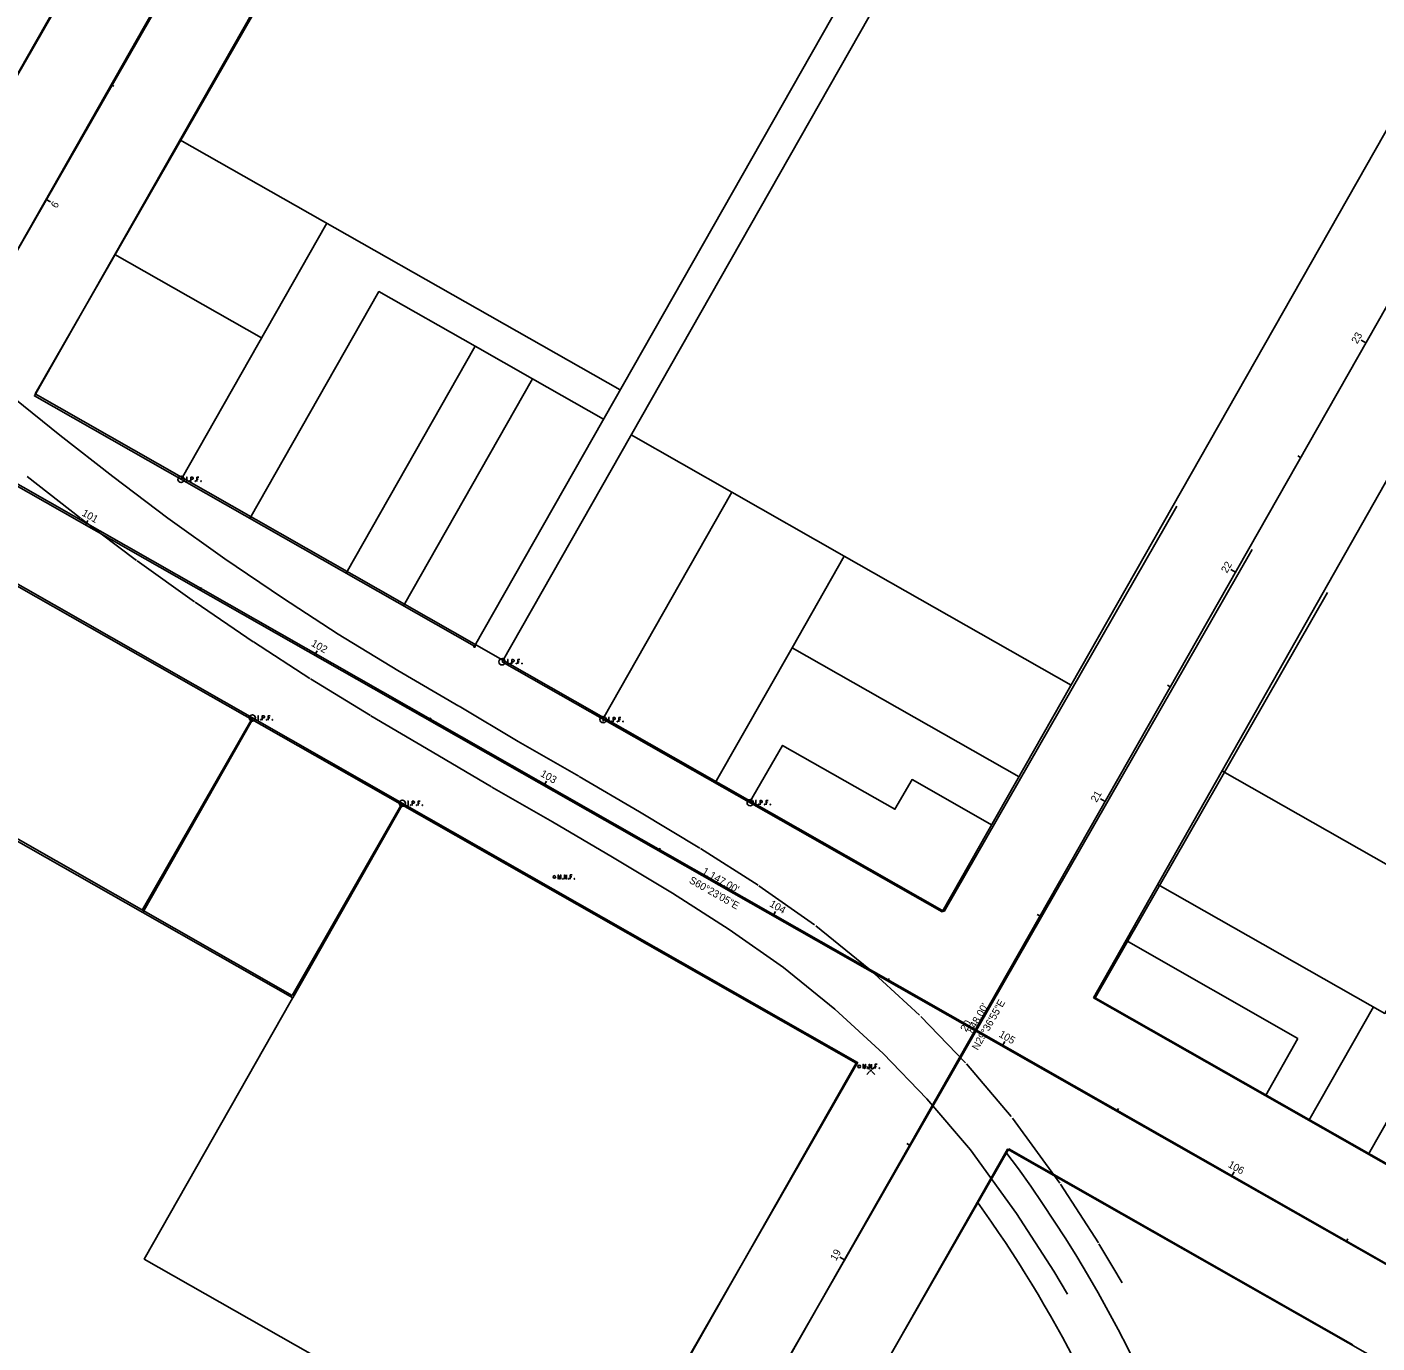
# Model space of a CAD drawing. Extents: x 119320 to 120701, y 385020 to 386199.
# Drawn here: x 119728 to 120240, y 385433 to 385932 of the extents above; entities that cross this region are included whole.
import ezdxf

# ---------------------------------------------------------------- set-up
doc = ezdxf.new("R2010")
doc.units = 0
for name, color, linetype in [('DV_X_Property_Line', 7, 'Continuous'), ('RW_X_CL', 7, 'Continuous'), ('RW_X_CL_100_Bearings', 7, 'Continuous'), ('RW_X_CL_100_Distances', 7, 'Continuous'), ('RW_X_CL_100_Stations', 7, 'Continuous'), ('RW_X_Esmt_RR', 7, 'Continuous'), ('RW_X_Fee_RW', 7, 'Continuous'), ('SC_Scratch1', 7, 'Continuous'), ('SV_X_Control_Cells_Found', 7, 'Continuous'), ('SV_X_Mon_Cells_Found', 7, 'Continuous'), ('SV_X_Shot_Marker', 7, 'Continuous')]:
    doc.layers.add(name, color=color, linetype=linetype)

msp = doc.modelspace()

# ---------------------------------------------------------------- linework, layer by layer
at = {"layer": 'DV_X_Property_Line'}
for p, q in [((119785.77, 385889.55), (119952.69, 385794.67)), ((119786.19, 385760.77), (119841.41, 385857.92)), ((119761.07, 385846.08), (119816.71, 385814.45)), ((119995.08, 385755.91), (119956.82, 385777.65)), ((119946.15, 385669.84), (119995.08, 385755.91)), ((119995.08, 385755.91), (120037.67, 385731.69)), ((119771.7, 385596.46), (119656.42, 385661.99)), ((120144.55, 385585.82), (120209.75, 385548.76)), ((120213.92, 385517.64), (120238.38, 385560.67)), ((120197.4, 385527.03), (120209.75, 385548.76))]:
    msp.add_line(p, q, dxfattribs=at)
for points in [[(119812.27, 385745.94), (119861.19, 385832.01), (119897.71, 385811.26)], [(119848.78, 385725.19), (119897.71, 385811.26), (119919.44, 385798.9)], [(119870.52, 385712.83), (119919.44, 385798.9), (119946.39, 385783.58)], [(120017.91, 385696.92), (120037.67, 385731.69), (120123.74, 385682.77)], [(119988.75, 385645.63), (120017.91, 385696.92), (120103.97, 385648)], [(119870.07, 385637.17), (119828.56, 385564.15), (119771.7, 385596.46), (119813.21, 385669.49)], [(120001.79, 385638.21), (120014.3, 385659.86), (120056.9, 385635.64), (120063.41, 385646.9), (120093.84, 385629.6)], [(120156.66, 385607.12), (120242.73, 385558.2), (120267.19, 385601.23), (120181.12, 385650.16)], [(119944.36, 385367.19), (119772.22, 385465.04), (119870.07, 385637.17)], [(120236.52, 385504.79), (120285.44, 385590.85), (120267.19, 385601.23)]]:
    msp.add_lwpolyline(points, dxfattribs=at)
for radius, start, end in [(494.53, 7.3661, 36.9032), (474.53, 17.8628, 35.8499)]:
    msp.add_arc((119703.54, 385208.72), radius, start, end, dxfattribs=at)
at = {"layer": 'RW_X_CL'}
for p, q in [((119897.55, 386152.97), (119478.5, 385415.75)), ((119880.14, 385187.44), (120299.2, 385924.66)), ((119491.69, 385890.22), (120488.85, 385323.4))]:
    msp.add_line(p, q, dxfattribs=at)
at = {"layer": 'RW_X_CL_100_Stations'}
for p, q in [((119759.68, 385910.42), (119760.72, 385909.83)), ((119734.97, 385866.95), (119736.71, 385865.96)), ((120235.45, 385812.52), (120233.71, 385813.5)), ((120210.74, 385769.05), (120209.7, 385769.64)), ((119749.89, 385743.45), (119750.88, 385745.19)), ((120186.03, 385725.58), (120184.3, 385726.57)), ((119793.36, 385718.74), (119793.95, 385719.78)), ((119836.82, 385694.03), (119837.81, 385695.77)), ((120161.33, 385682.11), (120160.28, 385682.7)), ((119880.29, 385669.32), (119880.88, 385670.36)), ((119923.76, 385644.61), (119924.75, 385646.35)), ((120136.62, 385638.64), (120134.88, 385639.63)), ((119967.23, 385619.9), (119967.82, 385620.95)), ((120010.7, 385595.19), (120011.68, 385596.93)), ((120111.91, 385595.18), (120110.87, 385595.77)), ((120054.16, 385570.49), (120054.76, 385571.53)), ((120087.2, 385551.71), (120085.46, 385552.7)), ((120097.63, 385545.78), (120098.62, 385547.52)), ((120141.1, 385521.07), (120141.69, 385522.11)), ((120062.49, 385508.24), (120061.45, 385508.83)), ((120184.57, 385496.36), (120185.56, 385498.1)), ((120228.04, 385471.65), (120228.63, 385472.69)), ((120037.78, 385464.77), (120036.04, 385465.76))]:
    msp.add_line(p, q, dxfattribs=at)
at = {"layer": 'RW_X_Esmt_RR'}
for p, q in [((119723.13, 385791.28), (119740.18, 385777.58)), ((119740.18, 385777.58), (119760.32, 385761.85)), ((119727.81, 385761.86), (119748.07, 385746.03)), ((119760.32, 385761.85), (119781.21, 385746.08)), ((119748.2, 385745.93), (119769.27, 385730.03)), ((119781.21, 385746.08), (119802.83, 385730.69)), ((119769.5, 385729.87), (119791.32, 385714.34)), ((119802.83, 385730.69), (119824.68, 385715.8)), ((119791.49, 385714.22), (119813.51, 385699.21)), ((119824.68, 385715.8), (119845.81, 385702.06)), ((119845.81, 385702.06), (119868.36, 385688.28)), ((119813.69, 385699.09), (119835.02, 385685.21)), ((119868.36, 385688.28), (119891.57, 385674.73)), ((119835.26, 385685.06), (119858.02, 385671.16)), ((119937.14, 385648.12), (119959.99, 385634.68)), ((119960.08, 385634.63), (119982.92, 385620.88)), ((119983.14, 385620.75), (120004.99, 385606.84)), ((120005.35, 385606.6), (120026.41, 385591.85)), ((120026.97, 385591.43), (120047, 385575.19)), ((120047.46, 385574.79), (120066.24, 385557.55)), ((120066.68, 385557.12), (120083.63, 385539.53)), ((120084.04, 385539.08), (120101.02, 385519.17)), ((120101.51, 385518.56), (120119.41, 385493.88)), ((120119.72, 385493.43), (120134.06, 385471.2))]:
    msp.add_line(p, q, dxfattribs=at)
for points in [[(119858.19, 385671.06), (119881.45, 385657.48), (119903.89, 385644.11)], [(119891.65, 385674.69), (119914.06, 385661.33), (119937.03, 385648.18)], [(119904.05, 385644.02), (119927.05, 385630.85), (119949.81, 385617.46), (119972.5, 385603.81), (119994.06, 385590.09), (120014.65, 385575.67), (120034.16, 385559.85), (120052.49, 385543.02), (120069.02, 385525.87), (120085.55, 385506.49), (120103.06, 385482.36), (120117.14, 385460.53), (120122.33, 385451.74)], [(120134.27, 385470.86), (120139.53, 385461.94), (120143.09, 385456.03)]]:
    msp.add_lwpolyline(points, dxfattribs=at)
at = {"layer": 'RW_X_Fee_RW'}
for points in [[(119507.99, 385918.9), (119673.17, 385825.01), (119869.11, 386169.71), (119816.95, 386199.36)], [(119926.24, 386136.66), (119730.55, 385792.4), (119897.47, 385697.52), (120093.16, 386041.78)], [(119907.9, 385691.58), (120074.82, 385596.7), (120270.51, 385940.97), (120103.59, 386035.85), (119907.9, 385691.58)], [(119507.18, 385399.44), (119697.94, 385735.02), (120042.2, 385539.33), (119851.45, 385203.75), (119507.18, 385399.44)], [(119920.57, 385191.78), (120099.58, 385506.71), (120443.85, 385311.02), (120394.43, 385224.08)]]:
    msp.add_lwpolyline(points, dxfattribs=at)
msp.add_lwpolyline([(120132.2, 385564.09), (120299.11, 385469.21), (120494.81, 385813.47), (120327.45, 385908.6)], close=True, dxfattribs=at)
at = {"layer": 'SC_Scratch1'}
for p, q in [((119530.56, 385576.63), (119762.43, 385980.86)), ((119559.19, 385560.21), (119791.06, 385964.44)), ((119730.86, 385793.18), (119819.68, 385948.02)), ((119730.86, 385793.18), (120075.54, 385596.83)), ((119685.77, 385780.89), (120087.8, 385551.87)), ((120075.54, 385596.83), (120163.77, 385750.65)), ((119698.02, 385735.93), (119813.24, 385670.29)), ((120087.8, 385551.87), (120192.4, 385734.23)), ((120132.89, 385564.16), (120221.02, 385717.81)), ((119771.45, 385597.43), (119813.24, 385670.29)), ((119813.24, 385670.29), (119870.09, 385637.91)), ((119656.23, 385663.06), (119828.3, 385565.04)), ((119828.3, 385565.04), (119870.09, 385637.91)), ((119870.09, 385637.91), (120042.7, 385539.58)), ((120132.89, 385564.16), (120263.23, 385489.92)), ((119960.53, 385330), (120087.8, 385551.87)), ((120087.8, 385551.87), (120246.89, 385461.24)), ((119931.9, 385346.42), (120042.8, 385539.75)), ((120030.95, 385386.44), (120100.05, 385506.91)), ((120100.05, 385506.91), (120230.56, 385432.57))]:
    msp.add_line(p, q, dxfattribs=at)
at = {"layer": 'SV_X_Control_Cells_Found'}
for p, q in [((120046.22, 385538.07), (120047.31, 385536.98)), ((120048.14, 385536.98), (120049.23, 385538.07)), ((120046.22, 385535.05), (120047.31, 385536.15)), ((120048.14, 385536.15), (120049.23, 385535.05))]:
    msp.add_line(p, q, dxfattribs=at)
for points in [[(119929.21, 385609.17), (119929.21, 385610.77), (119929.71, 385609.17), (119930.2, 385610.77), (119930.2, 385609.17)], [(119930.97, 385609.39), (119931.03, 385609.39), (119931.06, 385609.36), (119931.09, 385609.31), (119931.09, 385609.25), (119931.06, 385609.2), (119931.03, 385609.17), (119930.97, 385609.17), (119930.94, 385609.2), (119930.9, 385609.25), (119930.9, 385609.31), (119930.94, 385609.36), (119930.97, 385609.39)], [(119931.58, 385609.17), (119931.58, 385610.77), (119932.4, 385609.17), (119932.4, 385610.77)], [(119933.19, 385609.39), (119933.24, 385609.39), (119933.27, 385609.36), (119933.31, 385609.31), (119933.31, 385609.25), (119933.27, 385609.2), (119933.24, 385609.17), (119933.19, 385609.17), (119933.15, 385609.2), (119933.12, 385609.25), (119933.12, 385609.31), (119933.15, 385609.36), (119933.19, 385609.39)], [(119934.55, 385610.77), (119933.79, 385610.77), (119933.79, 385609.17)], [(119933.79, 385609.99), (119934.33, 385609.99)], [(119935.34, 385609.39), (119935.39, 385609.39), (119935.42, 385609.36), (119935.46, 385609.31), (119935.46, 385609.25), (119935.42, 385609.2), (119935.39, 385609.17), (119935.34, 385609.17), (119935.3, 385609.2), (119935.27, 385609.25), (119935.27, 385609.31), (119935.3, 385609.36), (119935.34, 385609.39)], [(120044.82, 385537.32), (120044.82, 385538.92), (120045.33, 385537.32), (120045.81, 385538.92), (120045.81, 385537.32)], [(120046.58, 385537.53), (120046.64, 385537.53), (120046.67, 385537.51), (120046.71, 385537.46), (120046.71, 385537.4), (120046.67, 385537.35), (120046.64, 385537.32), (120046.58, 385537.32), (120046.55, 385537.35), (120046.52, 385537.4), (120046.52, 385537.46), (120046.55, 385537.51), (120046.58, 385537.53)], [(120047.19, 385537.32), (120047.19, 385538.92), (120048.02, 385537.32), (120048.02, 385538.92)], [(120048.8, 385537.53), (120048.85, 385537.53), (120048.89, 385537.51), (120048.92, 385537.46), (120048.92, 385537.4), (120048.89, 385537.35), (120048.85, 385537.32), (120048.8, 385537.32), (120048.77, 385537.35), (120048.73, 385537.4), (120048.73, 385537.46), (120048.77, 385537.51), (120048.8, 385537.53)], [(120050.17, 385538.92), (120049.41, 385538.92), (120049.41, 385537.32)], [(120049.41, 385538.14), (120049.95, 385538.14)], [(120050.95, 385537.53), (120051, 385537.53), (120051.04, 385537.51), (120051.07, 385537.46), (120051.07, 385537.4), (120051.04, 385537.35), (120051, 385537.32), (120050.95, 385537.32), (120050.92, 385537.35), (120050.88, 385537.4), (120050.88, 385537.46), (120050.92, 385537.51), (120050.95, 385537.53)]]:
    msp.add_lwpolyline(points, dxfattribs=at)
for centre, radius in [((119927.77, 385609.98), 0.497), ((120043.38, 385538.13), 0.497), ((120047.73, 385536.57), 0.17)]:
    msp.add_circle(centre, radius, dxfattribs=at)
at = {"layer": 'SV_X_Mon_Cells_Found'}
msp.add_line((119946.24, 385669.76), (119946.24, 385668.88), dxfattribs=at)
for points in [[(119788.2, 385761.57), (119788.56, 385761.57)], [(119788.2, 385759.97), (119788.56, 385759.97)], [(119788.38, 385759.97), (119788.38, 385761.57)], [(119789.34, 385760.18), (119789.39, 385760.18), (119789.43, 385760.16), (119789.46, 385760.11), (119789.46, 385760.05), (119789.43, 385760), (119789.39, 385759.97), (119789.34, 385759.97), (119789.31, 385760), (119789.27, 385760.05), (119789.27, 385760.11), (119789.31, 385760.16), (119789.34, 385760.18)], [(119789.95, 385759.97), (119789.95, 385761.57), (119790.47, 385761.57), (119790.53, 385761.56), (119790.61, 385761.53), (119790.64, 385761.51), (119790.67, 385761.48), (119790.72, 385761.42), (119790.75, 385761.36), (119790.77, 385761.25), (119790.77, 385761.1), (119790.76, 385761.05), (119790.74, 385760.98), (119790.69, 385760.89), (119790.65, 385760.85), (119790.62, 385760.83), (119790.56, 385760.8), (119790.47, 385760.79), (119789.95, 385760.79)], [(119791.59, 385760.18), (119791.64, 385760.18), (119791.68, 385760.16), (119791.71, 385760.11), (119791.71, 385760.05), (119791.68, 385760), (119791.64, 385759.97), (119791.59, 385759.97), (119791.55, 385760), (119791.52, 385760.05), (119791.52, 385760.11), (119791.55, 385760.16), (119791.59, 385760.18)], [(119792.95, 385761.57), (119792.19, 385761.57), (119792.19, 385759.97)], [(119792.19, 385760.79), (119792.73, 385760.79)], [(119793.74, 385760.18), (119793.79, 385760.18), (119793.83, 385760.16), (119793.86, 385760.11), (119793.86, 385760.05), (119793.83, 385760), (119793.79, 385759.97), (119793.74, 385759.97), (119793.7, 385760), (119793.67, 385760.05), (119793.67, 385760.11), (119793.7, 385760.16), (119793.74, 385760.18)], [(119909.92, 385692.39), (119910.27, 385692.39)], [(119909.92, 385690.78), (119910.27, 385690.78)], [(119910.09, 385690.78), (119910.09, 385692.39)], [(119911.05, 385691), (119911.11, 385691), (119911.14, 385690.97), (119911.17, 385690.92), (119911.17, 385690.86), (119911.14, 385690.81), (119911.11, 385690.78), (119911.05, 385690.78), (119911.02, 385690.81), (119910.98, 385690.86), (119910.98, 385690.92), (119911.02, 385690.97), (119911.05, 385691)], [(119911.66, 385690.78), (119911.66, 385692.39), (119912.19, 385692.39), (119912.24, 385692.37), (119912.32, 385692.35), (119912.35, 385692.32), (119912.38, 385692.3), (119912.43, 385692.23), (119912.46, 385692.17), (119912.48, 385692.07), (119912.48, 385691.92), (119912.47, 385691.87), (119912.45, 385691.79), (119912.41, 385691.7), (119912.36, 385691.67), (119912.33, 385691.64), (119912.27, 385691.62), (119912.19, 385691.6), (119911.66, 385691.6)], [(119913.3, 385691), (119913.35, 385691), (119913.39, 385690.97), (119913.42, 385690.92), (119913.42, 385690.86), (119913.39, 385690.81), (119913.35, 385690.78), (119913.3, 385690.78), (119913.27, 385690.81), (119913.23, 385690.86), (119913.23, 385690.92), (119913.27, 385690.97), (119913.3, 385691)], [(119914.67, 385692.39), (119913.91, 385692.39), (119913.91, 385690.78)], [(119913.91, 385691.6), (119914.45, 385691.6)], [(119915.45, 385691), (119915.5, 385691), (119915.54, 385690.97), (119915.57, 385690.92), (119915.57, 385690.86), (119915.54, 385690.81), (119915.5, 385690.78), (119915.45, 385690.78), (119915.42, 385690.81), (119915.38, 385690.86), (119915.38, 385690.92), (119915.42, 385690.97), (119915.45, 385691)], [(119815.26, 385671.09), (119815.61, 385671.09)], [(119815.43, 385669.49), (119815.43, 385671.09)], [(119817, 385669.49), (119817, 385671.09), (119817.53, 385671.09), (119817.58, 385671.08), (119817.66, 385671.06), (119817.69, 385671.03), (119817.72, 385671), (119817.77, 385670.94), (119817.8, 385670.88), (119817.82, 385670.78), (119817.82, 385670.63), (119817.81, 385670.58), (119817.79, 385670.5), (119817.75, 385670.41), (119817.7, 385670.37), (119817.67, 385670.35), (119817.61, 385670.32), (119817.53, 385670.31), (119817, 385670.31)], [(119820.01, 385671.09), (119819.25, 385671.09), (119819.25, 385669.49)], [(119819.25, 385670.31), (119819.79, 385670.31)], [(119948.27, 385670.44), (119948.62, 385670.44)], [(119948.45, 385668.84), (119948.45, 385670.44)], [(119950.01, 385668.84), (119950.01, 385670.44), (119950.54, 385670.44), (119950.6, 385670.43), (119950.67, 385670.4), (119950.71, 385670.38), (119950.74, 385670.35), (119950.78, 385670.29), (119950.82, 385670.23), (119950.84, 385670.13), (119950.84, 385669.98), (119950.83, 385669.93), (119950.81, 385669.85), (119950.76, 385669.76), (119950.72, 385669.72), (119950.68, 385669.7), (119950.63, 385669.67), (119950.54, 385669.66), (119950.01, 385669.66)], [(119953.02, 385670.44), (119952.26, 385670.44), (119952.26, 385668.84)], [(119815.26, 385669.49), (119815.61, 385669.49)], [(119816.39, 385669.71), (119816.45, 385669.71), (119816.48, 385669.68), (119816.51, 385669.63), (119816.51, 385669.57), (119816.48, 385669.52), (119816.45, 385669.49), (119816.39, 385669.49), (119816.36, 385669.52), (119816.32, 385669.57), (119816.32, 385669.63), (119816.36, 385669.68), (119816.39, 385669.71)], [(119818.64, 385669.71), (119818.69, 385669.71), (119818.73, 385669.68), (119818.76, 385669.63), (119818.76, 385669.57), (119818.73, 385669.52), (119818.69, 385669.49), (119818.64, 385669.49), (119818.61, 385669.52), (119818.57, 385669.57), (119818.57, 385669.63), (119818.61, 385669.68), (119818.64, 385669.71)], [(119820.79, 385669.71), (119820.84, 385669.71), (119820.88, 385669.68), (119820.91, 385669.63), (119820.91, 385669.57), (119820.88, 385669.52), (119820.84, 385669.49), (119820.79, 385669.49), (119820.76, 385669.52), (119820.72, 385669.57), (119820.72, 385669.63), (119820.76, 385669.68), (119820.79, 385669.71)], [(119948.27, 385668.84), (119948.62, 385668.84)], [(119949.41, 385669.06), (119949.46, 385669.06), (119949.49, 385669.03), (119949.53, 385668.98), (119949.53, 385668.92), (119949.49, 385668.87), (119949.46, 385668.84), (119949.41, 385668.84), (119949.37, 385668.87), (119949.34, 385668.92), (119949.34, 385668.98), (119949.37, 385669.03), (119949.41, 385669.06)], [(119951.65, 385669.06), (119951.71, 385669.06), (119951.74, 385669.03), (119951.78, 385668.98), (119951.78, 385668.92), (119951.74, 385668.87), (119951.71, 385668.84), (119951.65, 385668.84), (119951.62, 385668.87), (119951.59, 385668.92), (119951.59, 385668.98), (119951.62, 385669.03), (119951.65, 385669.06)], [(119952.26, 385669.66), (119952.8, 385669.66)], [(119953.8, 385669.06), (119953.86, 385669.06), (119953.89, 385669.03), (119953.93, 385668.98), (119953.93, 385668.92), (119953.89, 385668.87), (119953.86, 385668.84), (119953.8, 385668.84), (119953.77, 385668.87), (119953.74, 385668.92), (119953.74, 385668.98), (119953.77, 385669.03), (119953.8, 385669.06)], [(119872.11, 385638.71), (119872.46, 385638.71)], [(119872.11, 385637.11), (119872.46, 385637.11)], [(119872.28, 385637.11), (119872.28, 385638.71)], [(119873.24, 385637.32), (119873.3, 385637.32), (119873.33, 385637.3), (119873.36, 385637.25), (119873.36, 385637.18), (119873.33, 385637.13), (119873.3, 385637.11), (119873.24, 385637.11), (119873.21, 385637.13), (119873.18, 385637.18), (119873.18, 385637.25), (119873.21, 385637.3), (119873.24, 385637.32)], [(119873.85, 385637.11), (119873.85, 385638.71), (119874.38, 385638.71), (119874.43, 385638.7), (119874.51, 385638.67), (119874.54, 385638.64), (119874.58, 385638.62), (119874.62, 385638.56), (119874.65, 385638.49), (119874.67, 385638.39), (119874.67, 385638.24), (119874.66, 385638.19), (119874.64, 385638.12), (119874.6, 385638.03), (119874.55, 385637.99), (119874.52, 385637.96), (119874.47, 385637.94), (119874.38, 385637.93), (119873.85, 385637.93)], [(119875.49, 385637.32), (119875.55, 385637.32), (119875.58, 385637.3), (119875.61, 385637.25), (119875.61, 385637.18), (119875.58, 385637.13), (119875.55, 385637.11), (119875.49, 385637.11), (119875.46, 385637.13), (119875.42, 385637.18), (119875.42, 385637.25), (119875.46, 385637.3), (119875.49, 385637.32)], [(119876.86, 385638.71), (119876.1, 385638.71), (119876.1, 385637.11)], [(119876.1, 385637.93), (119876.64, 385637.93)], [(119877.64, 385637.32), (119877.69, 385637.32), (119877.73, 385637.3), (119877.76, 385637.25), (119877.76, 385637.18), (119877.73, 385637.13), (119877.69, 385637.11), (119877.64, 385637.11), (119877.61, 385637.13), (119877.57, 385637.18), (119877.57, 385637.25), (119877.61, 385637.3), (119877.64, 385637.32)], [(120004.05, 385638.94), (120004.4, 385638.94)], [(120004.05, 385637.34), (120004.4, 385637.34)], [(120004.22, 385637.34), (120004.22, 385638.94)], [(120005.18, 385637.55), (120005.24, 385637.55), (120005.27, 385637.53), (120005.3, 385637.48), (120005.3, 385637.42), (120005.27, 385637.37), (120005.24, 385637.34), (120005.18, 385637.34), (120005.15, 385637.37), (120005.11, 385637.42), (120005.11, 385637.48), (120005.15, 385637.53), (120005.18, 385637.55)], [(120005.79, 385637.34), (120005.79, 385638.94), (120006.32, 385638.94), (120006.37, 385638.93), (120006.45, 385638.9), (120006.48, 385638.88), (120006.51, 385638.85), (120006.56, 385638.79), (120006.59, 385638.73), (120006.61, 385638.62), (120006.61, 385638.47), (120006.6, 385638.42), (120006.58, 385638.35), (120006.54, 385638.26), (120006.49, 385638.22), (120006.46, 385638.2), (120006.4, 385638.17), (120006.32, 385638.16), (120005.79, 385638.16)], [(120007.43, 385637.55), (120007.48, 385637.55), (120007.52, 385637.53), (120007.55, 385637.48), (120007.55, 385637.42), (120007.52, 385637.37), (120007.48, 385637.34), (120007.43, 385637.34), (120007.4, 385637.37), (120007.36, 385637.42), (120007.36, 385637.48), (120007.4, 385637.53), (120007.43, 385637.55)], [(120008.8, 385638.94), (120008.04, 385638.94), (120008.04, 385637.34)], [(120008.04, 385638.16), (120008.58, 385638.16)], [(120009.58, 385637.55), (120009.63, 385637.55), (120009.67, 385637.53), (120009.7, 385637.48), (120009.7, 385637.42), (120009.67, 385637.37), (120009.63, 385637.34), (120009.58, 385637.34), (120009.55, 385637.37), (120009.51, 385637.42), (120009.51, 385637.48), (120009.55, 385637.53), (120009.58, 385637.55)]]:
    msp.add_lwpolyline(points, dxfattribs=at)
for centre, radius in [((119786.19, 385760.77), 1.2), ((119907.9, 385691.58), 1.2), ((119813.24, 385670.29), 1.2), ((119946.24, 385669.64), 1.2), ((119946.24, 385670.29), 0.16), ((120002.03, 385638.14), 1.2), ((119870.09, 385637.91), 1.2)]:
    msp.add_circle(centre, radius, dxfattribs=at)
at = {"layer": 'SV_X_Shot_Marker'}
for p, q in [((119896.98, 385697.4), (119897.98, 385697.4)), ((119897.48, 385697.9), (119897.48, 385696.9)), ((119897.48, 385697.4), (119897.48, 385697.4))]:
    msp.add_line(p, q, dxfattribs=at)

# ---------------------------------------------------------------- texts
at = {"layer": 'RW_X_CL_100_Bearings'}
for s, rotation, p in [('S60°23\'05"E', 330.3847, (119978.58, 385607.93)), ('N29°36\'55"E', 60.3847, (120088.35, 385544.02))]:
    msp.add_text(s, height=2.8, rotation=rotation, dxfattribs=at).set_placement(p)
at = {"layer": 'RW_X_CL_100_Distances'}
for s, rotation, p in [("1,147.00'", 330.3847, (119983.54, 385611.35)), ("848.00'", 60.3847, (120086.46, 385550.48))]:
    msp.add_text(s, height=2.8, rotation=rotation, dxfattribs=at).set_placement(p)
at = {"layer": 'RW_X_CL_100_Stations'}
for s, rotation, p in [('9', 240.3847, (119737.63, 385866.58)), ('23', 60.3847, (120232.25, 385811.94)), ('101', 330.3847, (119748.32, 385747.21)), ('22', 60.3847, (120182.83, 385724.99)), ('102', 330.3847, (119835.27, 385697.79)), ('103', 330.3847, (119922.21, 385648.37)), ('21', 60.3847, (120133.4, 385638.05)), ('104', 330.3847, (120009.08, 385598.99)), ('20', 60.3847, (120083.96, 385551.07)), ('105', 330.3847, (120096.08, 385549.54)), ('106', 330.3847, (120182.97, 385500.14)), ('19', 60.3847, (120034.57, 385464.17))]:
    msp.add_text(s, height=2.8, rotation=rotation, dxfattribs=at).set_placement(p)

doc.saveas('drawing.dxf')
